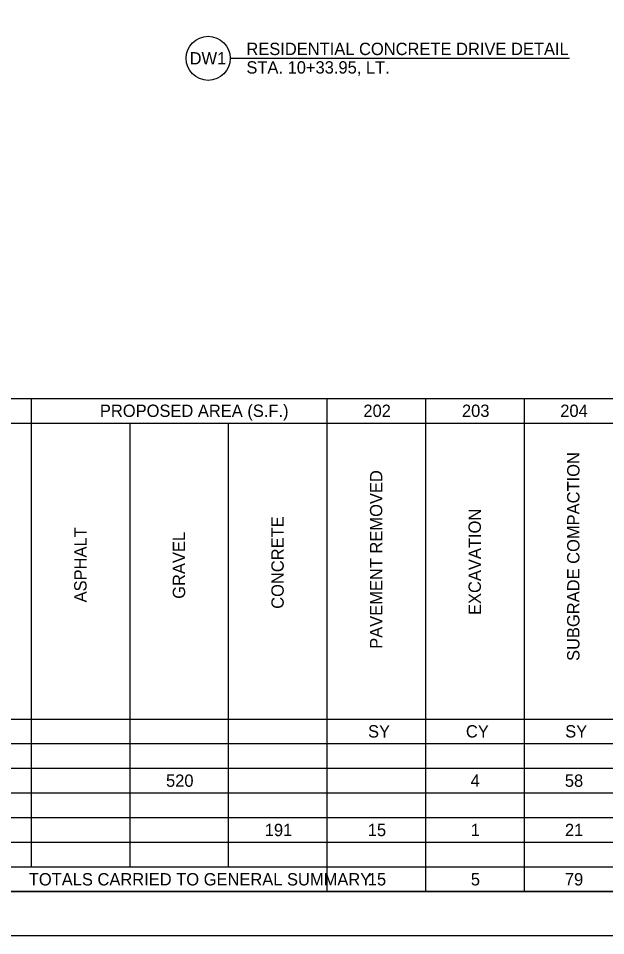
# Model space of a CAD drawing. Extents: x -1.2 to 34, y 0 to 22.
# Drawn here: x 20.66 to 27.33, y 0 to 10.42 of the extents above; entities that cross this region are included whole.
import ezdxf

# ---------------------------------------------------------------- set-up
doc = ezdxf.new("R2010")
doc.units = 0
for name, color, linetype in [('SH_Border', 7, 'Continuous'), ('SH_Cut_Line', 7, 'Continuous'), ('SH_Data', 7, 'Continuous'), ('SH_Text', 7, 'Continuous')]:
    doc.layers.add(name, color=color, linetype=linetype)

msp = doc.modelspace()

# ---------------------------------------------------------------- linework, layer by layer
at = {"layer": 'SH_Border'}
msp.add_lwpolyline([(1.5, 21.5), (33.5, 21.5), (33.5, 0.5), (1.5, 0.5)], close=True, dxfattribs=at)
at = {"layer": 'SH_Cut_Line'}
msp.add_lwpolyline([(0, 0), (34, 0), (34, 22), (0, 22)], close=True, dxfattribs=at)
at = {"layer": 'SH_Data'}
for p, q in [((10.456, 6.1), (32, 6.1)), ((20.8, 6.1), (20.8, 0.78)), ((24.16, 6.1), (24.16, 0.5)), ((25.28, 6.1), (25.28, 0.5)), ((26.4, 6.1), (26.4, 0.5)), ((15.48, 5.82), (32, 5.82)), ((21.92, 5.82), (21.92, 0.78)), ((23.04, 5.82), (23.04, 0.78)), ((13.932, 2.46), (32, 2.46)), ((10.456, 2.18), (32, 2.18)), ((10.456, 1.9), (32, 1.9)), ((10.456, 1.62), (32, 1.62)), ((10.456, 1.34), (32, 1.34)), ((10.456, 1.06), (32, 1.06)), ((10.456, 0.78), (32, 0.78)), ((10.456, 0.5), (32, 0.5))]:
    msp.add_line(p, q, dxfattribs=at)
at = {"layer": 'SH_Text'}
msp.add_line((23.062, 9.962), (26.918, 9.962), dxfattribs=at)
msp.add_circle((22.812, 9.962), 0.25, dxfattribs=at)

# ---------------------------------------------------------------- texts
for s, p in [('RESIDENTIAL CONCRETE DRIVE DETAIL', (23.246, 9.999)), ('DW1', (22.601, 9.892)), ('STA. 10+33.95, LT.', (23.246, 9.789)), ('PROPOSED AREA (S.F.)', (21.582, 5.89)), ('202', (24.575, 5.89)), ('203', (25.695, 5.89)), ('204', (26.812, 5.89)), ('SY', (24.628, 2.25)), ('CY', (25.74, 2.25)), ('SY', (26.868, 2.25)), ('520', (22.333, 1.69)), ('4', (25.793, 1.69)), ('58', (26.864, 1.69)), ('191', (23.455, 1.13)), ('15', (24.625, 1.13)), ('1', (25.795, 1.13)), ('21', (26.865, 1.13)), ('TOTALS CARRIED TO GENERAL SUMMARY', (20.774, 0.57)), ('15', (24.625, 0.57)), ('5', (25.796, 0.57)), ('79', (26.864, 0.57))]:
    msp.add_text(s, height=0.14, dxfattribs=at).set_placement(p)
for s, p in [('SUBGRADE COMPACTION', (27.03, 3.119)), ('PAVEMENT REMOVED', (24.79, 3.257)), ('EXCAVATION', (25.91, 3.641)), ('CONCRETE', (23.67, 3.711)), ('ASPHALT', (21.43, 3.784)), ('GRAVEL', (22.55, 3.825))]:
    msp.add_text(s, height=0.14, rotation=90, dxfattribs=at).set_placement(p)

doc.saveas('drawing.dxf')
